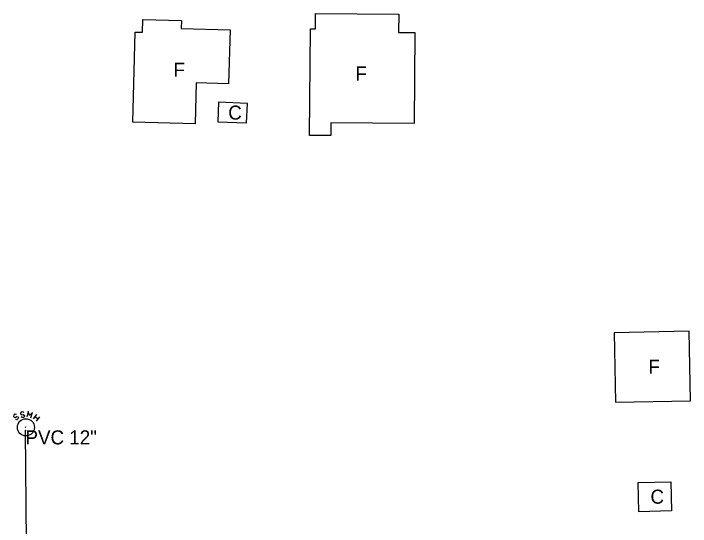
# Model space of a CAD drawing. Extents: x 1304270 to 1306561, y 1876019 to 1876752.
# Drawn here: x 1305621.6 to 1305862.6, y 1876566.4 to 1876749.2 of the extents above; entities that cross this region are included whole.
import ezdxf

# ---------------------------------------------------------------- set-up
doc = ezdxf.new("R2010")
doc.units = 0
for name, color, linetype in [('S_BUILDING', 7, 'Continuous'), ('S_BUILDING_ANNOT', 7, 'Continuous'), ('S_SANITARY_SEWER', 7, 'Continuous'), ('S_SANITARY_SEWER_ANNOT', 7, 'Continuous'), ('S_UTL_PT_SYM', 7, 'Continuous')]:
    doc.layers.add(name, color=color, linetype=linetype)

msp = doc.modelspace()

# ---------------------------------------------------------------- linework, layer by layer
at = {"layer": 'S_BUILDING'}
for points in [[(1305726.98, 1876705.73), (1305727.31, 1876743.65), (1305729.07, 1876743.64), (1305729.12, 1876749.15), (1305758.72, 1876748.9), (1305758.66, 1876742.41), (1305764.45, 1876742.36), (1305764.17, 1876709.93), (1305734.53, 1876710.19), (1305734.49, 1876705.66)], [(1305686.2, 1876709.83), (1305664, 1876710.46), (1305664.91, 1876742.53), (1305667.5, 1876742.46), (1305667.63, 1876747.05), (1305681.39, 1876746.66), (1305681.31, 1876743.86), (1305698.68, 1876743.37), (1305698.13, 1876724.1), (1305686.62, 1876724.42)], [(1305704.81, 1876717.15), (1305694.58, 1876717.52), (1305694.33, 1876710.56), (1305704.56, 1876710.19)], [(1305862.08, 1876635.92), (1305835.43, 1876635.41), (1305835.91, 1876610.69), (1305862.55, 1876611.2)], [(1305855.54, 1876582.34), (1305855.82, 1876571.95), (1305844.18, 1876571.63), (1305843.9, 1876582.03)]]:
    msp.add_lwpolyline(points, close=True, dxfattribs=at)
at = {"layer": 'S_SANITARY_SEWER'}
for p, q in [((1305622.2, 1876606.39), (1305621.66, 1876606.01)), ((1305622.63, 1876606.32), (1305622.2, 1876606.39)), ((1305628.64, 1876604.77), (1305629.88, 1876606.24)), ((1305621.66, 1876606.01), (1305621.58, 1876605.62)), ((1305621.58, 1876605.62), (1305621.78, 1876605.35)), ((1305621.78, 1876605.35), (1305622.2, 1876605.23)), ((1305622.2, 1876605.23), (1305622.75, 1876605.58)), ((1305622.75, 1876604.42), (1305622.36, 1876604.5)), ((1305622.75, 1876605.58), (1305623.21, 1876605.5)), ((1305623.29, 1876604.81), (1305622.75, 1876604.42)), ((1305623.21, 1876605.5), (1305623.37, 1876605.23)), ((1305623.37, 1876605.23), (1305623.29, 1876604.81)), ((1305629.3, 1876605.54), (1305630.26, 1876604.73)), ((1305630.85, 1876605.43), (1305629.61, 1876603.95)), ((1305627.46, 1876413.95), (1305625.83, 1876600.63))]:
    msp.add_line(p, q, dxfattribs=at)
for points in [[(1305625.3, 1876606.94), (1305624.96, 1876607.21), (1305624.3, 1876607.13), (1305624.06, 1876606.78), (1305624.1, 1876606.47), (1305624.45, 1876606.16), (1305625.07, 1876606.28), (1305625.46, 1876605.97), (1305625.5, 1876605.66), (1305625.23, 1876605.27), (1305624.61, 1876605.19), (1305624.26, 1876605.46)], [(1305627.75, 1876605.08), (1305628.29, 1876606.94), (1305627.24, 1876605.93), (1305626.85, 1876607.36), (1305626.31, 1876605.5)]]:
    msp.add_lwpolyline(points, dxfattribs=at)
msp.add_circle((1305625.99, 1876601.7), 3.05, dxfattribs=at)
at = {"layer": 'S_UTL_PT_SYM'}
for points in [[(1305625.87, 1876601.82), (1305625.87, 1876601.87), (1305625.87, 1876601.82), (1305625.82, 1876601.82), (1305625.87, 1876601.82), (1305625.87, 1876601.77), (1305625.87, 1876601.82), (1305625.92, 1876601.82)], [(1305625.83, 1876600.63), (1305625.83, 1876600.68), (1305625.83, 1876600.63), (1305625.78, 1876600.63), (1305625.83, 1876600.63), (1305625.83, 1876600.58), (1305625.83, 1876600.63), (1305625.88, 1876600.63)]]:
    msp.add_lwpolyline(points, dxfattribs=at)

# ---------------------------------------------------------------- texts
at = {"layer": 'S_BUILDING_ANNOT'}
for s, p in [('F', (1305678.51, 1876726.6)), ('F', (1305743.28, 1876725.28)), ('C', (1305698.01, 1876711.35)), ('F', (1305847.56, 1876620.8)), ('C', (1305848.31, 1876574.5))]:
    msp.add_text(s, height=5, dxfattribs=at).set_placement(p)
at = {"layer": 'S_SANITARY_SEWER_ANNOT'}
msp.add_text('PVC 12"', height=5, dxfattribs=at).set_placement((1305625.83, 1876595.63))

doc.saveas('drawing.dxf')
